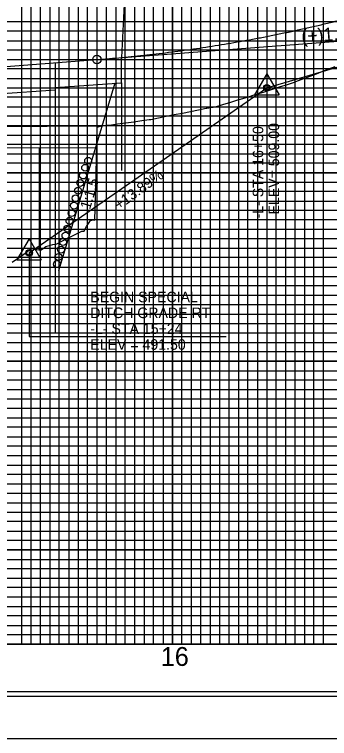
# Model space of a CAD drawing. Extents: x 573715 to 575626, y -55474 to -54374.
# Drawn here: x 574498.5 to 574665.5, y -55474.4 to -55090.5 of the extents above; entities that cross this region are included whole.
import ezdxf

# ---------------------------------------------------------------- set-up
doc = ezdxf.new("R2010")
doc.units = 0
for name, color, linetype in [('Default', 7, 'Continuous'), ('Exist Profile Cell', 7, 'Continuous'), ('Exist Vertical Profile Ground Line', 7, 'Continuous'), ('Exist Vertical Profile Horizontal Axis Label Major', 7, 'Continuous'), ('Prop Roadway Bridge', 7, 'Continuous'), ('Prop Vertical Profile Curve Label', 7, 'Continuous'), ('Prop Vertical Profile Ditch Grade Right', 7, 'Continuous'), ('Prop Vertical Profile Ditch Grade Right Label', 7, 'Continuous'), ('Prop Vertical Profile Grade', 7, 'Continuous'), ('Prop Vertical Profile Grade Label', 7, 'Continuous'), ('Prop VPI Label', 7, 'Continuous'), ('Sheet Cutting Line CELL', 7, 'Continuous'), ('Sheet DOT Grid CELL', 7, 'Continuous'), ('Sheet Layout Profile Border', 7, 'Continuous'), ('Sheet Plot Border Inside CELL', 7, 'Continuous'), ('Sheet Plot Border Outside CELL', 7, 'Continuous'), ('Sheet Profile CELL', 7, 'Continuous'), ('Sheet Profile Grid Major CELL', 7, 'Continuous'), ('Sheet Profile Grid Middle CELL', 7, 'Continuous'), ('Sheet Profile Grid Minor CELL', 7, 'Continuous')]:
    doc.layers.add(name, color=color, linetype=linetype)

msp = doc.modelspace()

# ---------------------------------------------------------------- linework, layer by layer
at = {"layer": 'Default'}
for p, q in [((574451.39, -55150.07), (574542.22, -55149.62)), ((574542.22, -55149.62), (574542.22, -55161.07)), ((574451.39, -55161.42), (574542.22, -55161.07)), ((574511.72, -55215.29), (574511.72, -55161.19))]:
    msp.add_line(p, q, dxfattribs=at)
at = {"layer": 'Exist Profile Cell'}
msp.add_line((573982.27, -55224.42), (575001.21, -55224.42), dxfattribs=at)
at = {"layer": 'Exist Vertical Profile Ground Line'}
msp.add_lwpolyline([(574497.4, -55221.8), (574501.76, -55218.83), (574503.47, -55217.66), (574506.04, -55215.68), (574507.55, -55214.53), (574509.69, -55214.98), (574510.33, -55215.08), (574512.36, -55215.4), (574513.67, -55214.64), (574514.62, -55213.84), (574515.08, -55213.45), (574518.91, -55212.56), (574520.92, -55212.09), (574523.2, -55210.94), (574527.49, -55208.8), (574531.78, -55206.66), (574534.29, -55205.41), (574535.47, -55205.43), (574536.07, -55204.23), (574536.71, -55202.96), (574538.79, -55199.75), (574540.36, -55199.33), (574541.14, -55199.65), (574541.75, -55174.95), (574542.35, -55150.23), (574544.65, -55149.63), (574547.64, -55149.29), (574548.94, -55149.12), (574553.23, -55148.54), (574557.52, -55147.95), (574561.81, -55147.37), (574566.1, -55146.79), (574569.92, -55146.27), (574570.39, -55146.19), (574570.87, -55146.12), (574574.89, -55145.31), (574578.96, -55144.49), (574583.25, -55143.63), (574587.54, -55142.77), (574591.83, -55141.91), (574596.12, -55141.05), (574600.05, -55140.26), (574600.41, -55140.2), (574604.87, -55139.51), (574606.92, -55138.93), (574608.99, -55138.28), (574613.28, -55136.93), (574616.99, -55135.76), (574617.57, -55135.6), (574622.07, -55134.32), (574626.15, -55133.03), (574630.44, -55131.67), (574634.73, -55130.31), (574639.02, -55128.94), (574643.3, -55127.57), (574646.95, -55126.4), (574647.68, -55126.11), (574651.97, -55124.45), (574655.22, -55123.19), (574658.56, -55121.9), (574661.89, -55120.61), (574665.23, -55119.33), (574668.57, -55118.05)], dxfattribs=at)
at = {"layer": 'Prop Roadway Bridge'}
for p, q in [((574555.29, -55126.77), (574555.29, -55113.31)), ((574520.29, -55129.22), (574520.29, -55116.08)), ((574520.29, -55129.22), (574555.29, -55126.77)), ((574551.76, -55127.02), (574521.93, -55226.45)), ((574555.29, -55126.77), (574555.29, -55173.26)), ((574450.29, -55135.37), (574520.29, -55130.47)), ((574520.29, -55259.24), (574520.29, -55129.22))]:
    msp.add_line(p, q, dxfattribs=at)
for centre in [(574537.6, -55168.09), (574535.99, -55171.81), (574534.87, -55175.9), (574533.38, -55179.86), (574532.27, -55183.95), (574530.91, -55187.92), (574530.04, -55191.88), (574528.8, -55195.85), (574527.69, -55199.93), (574526.57, -55204.02), (574524.22, -55211.21), (574525.58, -55207.74), (574523.23, -55215.18), (574521.12, -55222.86), (574521.87, -55219.14)]:
    msp.add_circle(centre, 1.83, dxfattribs=at)
at = {"layer": 'Prop Vertical Profile Curve Label'}
msp.add_circle((574542.27, -55114.41), 2.25, dxfattribs=at)
at = {"layer": 'Prop Vertical Profile Ditch Grade Right'}
msp.add_lwpolyline([(574506.27, -55216.92), (574632.27, -55129.42), (574782.27, -55085.27), (574907.27, -55010.97)], dxfattribs=at)
at = {"layer": 'Prop Vertical Profile Ditch Grade Right Label'}
for p, q in [((574632.27, -55121.94), (574625.82, -55133.14)), ((574632.27, -55121.94), (574638.77, -55133.14)), ((574632.27, -55129.42), (574632.27, -55200.04)), ((574632.27, -55129.42), (574632.27, -55200.04)), ((574625.82, -55133.14), (574638.77, -55133.14)), ((574506.27, -55209.44), (574499.82, -55220.64)), ((574506.27, -55209.44), (574512.77, -55220.64)), ((574506.27, -55216.92), (574506.27, -55261.31)), ((574499.82, -55220.64), (574512.77, -55220.64)), ((574506.27, -55261.31), (574610.74, -55261.31))]:
    msp.add_line(p, q, dxfattribs=at)
for centre, radius in [((574632.27, -55129.42), 1.75), ((574632.27, -55129.42), 1.2), ((574506.27, -55216.92), 1.75), ((574506.27, -55216.92), 1.2)]:
    msp.add_circle(centre, radius, dxfattribs=at)
at = {"layer": 'Prop Vertical Profile Grade'}
msp.add_line((574452.27, -55121.23), (574542.27, -55114.41), dxfattribs=at)
msp.add_spline([(574542.27, -55114.41), (574548.87, -55113.88), (574555.47, -55113.3), (574562.07, -55112.65), (574568.67, -55111.95), (574575.27, -55111.18), (574581.87, -55110.36), (574588.47, -55109.48), (574595.07, -55108.54), (574601.67, -55107.54), (574608.27, -55106.49), (574614.87, -55105.37), (574621.47, -55104.2), (574628.07, -55102.97), (574634.67, -55101.68), (574641.27, -55100.33), (574647.87, -55098.92), (574654.47, -55097.45), (574661.07, -55095.93), (574667.67, -55094.34), (574674.27, -55092.7), (574680.87, -55091), (574687.47, -55089.24), (574694.07, -55087.42), (574700.67, -55085.54), (574707.27, -55083.61), (574713.87, -55081.62), (574720.47, -55079.56), (574727.07, -55077.45), (574733.67, -55075.28), (574740.27, -55073.05), (574746.87, -55070.77), (574753.47, -55068.42), (574760.07, -55066.02), (574766.67, -55063.56), (574773.27, -55061.03), (574779.87, -55058.45), (574786.47, -55055.82), (574793.07, -55053.12), (574799.67, -55050.36), (574806.27, -55047.55), (574812.87, -55044.68), (574819.47, -55041.74), (574826.07, -55038.75), (574832.67, -55035.71), (574839.27, -55032.6), (574845.87, -55029.43), (574852.47, -55026.21), (574859.07, -55022.93), (574865.67, -55019.58), (574872.27, -55016.18)], degree=3, dxfattribs=at)
at = {"layer": 'Prop VPI Label'}
for p, q in [((574562.55, -54963.47), (574555.29, -55113.31)), ((574542.27, -55114.41), (574704.53, -55102.13))]:
    msp.add_line(p, q, dxfattribs=at)
at = {"layer": 'Sheet Cutting Line CELL'}
msp.add_line((573715.27, -55474.42), (575399.27, -55474.42), dxfattribs=at)
at = {"layer": 'Sheet DOT Grid CELL'}
for p, q in [((574532.27, -54399.42), (574532.27, -55424.42)), ((574582.27, -54399.42), (574582.27, -55424.42)), ((574632.27, -54399.42), (574632.27, -55424.42)), ((573882.27, -55124.42), (575382.27, -55124.42)), ((573882.27, -55174.42), (575382.27, -55174.42)), ((573882.27, -55224.42), (575382.27, -55224.42)), ((573882.27, -55274.42), (575382.27, -55274.42)), ((573882.27, -55324.42), (575382.27, -55324.42)), ((573882.27, -55374.42), (575382.27, -55374.42))]:
    msp.add_line(p, q, dxfattribs=at)
at = {"layer": 'Sheet Layout Profile Border'}
msp.add_lwpolyline([(573932.27, -54399.42), (573932.27, -55424.42), (575332.27, -55424.42), (575332.27, -54536.97), (575182.22, -54536.97), (575182.22, -54399.42)], close=True, dxfattribs=at)
at = {"layer": 'Sheet Plot Border Inside CELL'}
msp.add_lwpolyline([(575394.77, -54396.87), (573728.27, -54396.87), (573728.27, -55451.97), (575394.77, -55451.97)], close=True, dxfattribs=at)
msp.add_lwpolyline([(575394.77, -54396.87), (573728.27, -54396.87), (573728.27, -55451.97), (575394.77, -55451.97)], close=True, dxfattribs=at)
at = {"layer": 'Sheet Plot Border Outside CELL'}
msp.add_lwpolyline([(575399.27, -54374.42), (573715.27, -54374.42), (573715.27, -55474.42), (575399.27, -55474.42)], close=True, dxfattribs=at)
at = {"layer": 'Sheet Profile CELL'}
msp.add_line((575382.27, -55424.42), (573882.27, -55424.42), dxfattribs=at)
msp.add_lwpolyline([(575382.27, -54399.42), (573882.27, -54399.42), (573882.27, -55449.42), (575382.27, -55449.42)], close=True, dxfattribs=at)
at = {"layer": 'Sheet Profile Grid Major CELL'}
for points in [[(574532.27, -54399.42), (574532.27, -55424.42), (574582.27, -55424.42), (574582.27, -54399.42)], [(574632.27, -54399.42), (574632.27, -55424.42), (574682.27, -55424.42), (574682.27, -54399.42)], [(575382.27, -55174.42), (573882.27, -55174.42), (573882.27, -55124.42), (575382.27, -55124.42)], [(575382.27, -55274.42), (573882.27, -55274.42), (573882.27, -55224.42), (575382.27, -55224.42)], [(575382.27, -55374.42), (573882.27, -55374.42), (573882.27, -55324.42), (575382.27, -55324.42)]]:
    msp.add_lwpolyline(points, dxfattribs=at)
at = {"layer": 'Sheet Profile Grid Middle CELL'}
for points in [[(574507.27, -54399.42), (574507.27, -55424.42), (574557.27, -55424.42), (574557.27, -54399.42)], [(574607.27, -54399.42), (574607.27, -55424.42), (574657.27, -55424.42), (574657.27, -54399.42)], [(575382.27, -55099.42), (573882.27, -55099.42), (573882.27, -55149.42), (575382.27, -55149.42)], [(575382.27, -55199.42), (573882.27, -55199.42), (573882.27, -55249.42), (575382.27, -55249.42)], [(575382.27, -55299.42), (573882.27, -55299.42), (573882.27, -55349.42), (575382.27, -55349.42)], [(575382.27, -55399.42), (573882.27, -55399.42)]]:
    msp.add_lwpolyline(points, dxfattribs=at)
at = {"layer": 'Sheet Profile Grid Minor CELL'}
for points in [[(574502.27, -54399.42), (574502.27, -55424.42), (574512.27, -55424.42), (574512.27, -54399.42)], [(574517.27, -54399.42), (574517.27, -55424.42), (574522.27, -55424.42), (574522.27, -54399.42)], [(574527.27, -54399.42), (574527.27, -55424.42), (574537.27, -55424.42), (574537.27, -54399.42)], [(574542.27, -54399.42), (574542.27, -55424.42), (574547.27, -55424.42), (574547.27, -54399.42)], [(574552.27, -54399.42), (574552.27, -55424.42), (574562.27, -55424.42), (574562.27, -54399.42)], [(574567.27, -54399.42), (574567.27, -55424.42), (574572.27, -55424.42), (574572.27, -54399.42)], [(574577.27, -54399.42), (574577.27, -55424.42), (574587.27, -55424.42), (574587.27, -54399.42)], [(574592.27, -54399.42), (574592.27, -55424.42), (574597.27, -55424.42), (574597.27, -54399.42)], [(574602.27, -54399.42), (574602.27, -55424.42), (574612.27, -55424.42), (574612.27, -54399.42)], [(574617.27, -54399.42), (574617.27, -55424.42), (574622.27, -55424.42), (574622.27, -54399.42)], [(574627.27, -54399.42), (574627.27, -55424.42), (574637.27, -55424.42), (574637.27, -54399.42)], [(574642.27, -54399.42), (574642.27, -55424.42)], [(574652.27, -54400.02), (574652.27, -55424.42), (574662.27, -55424.42), (574662.27, -54399.42)], [(574642.27, -55424.42), (574647.27, -55424.42), (574647.27, -54400.02)], [(575332.27, -55094.42), (573932.27, -55094.42), (573932.27, -55104.42), (575332.27, -55104.42)], [(575332.27, -55109.42), (573932.27, -55109.42), (573932.27, -55114.42), (575332.27, -55114.42)], [(575332.27, -55119.42), (573932.27, -55119.42), (573932.27, -55129.42), (575332.27, -55129.42)], [(575332.27, -55134.42), (573932.27, -55134.42), (573932.27, -55139.42), (575332.27, -55139.42)], [(575332.27, -55144.42), (573932.27, -55144.42), (573932.27, -55154.42), (575332.27, -55154.42)], [(575332.27, -55159.42), (573932.27, -55159.42), (573932.27, -55164.42), (575332.27, -55164.42)], [(575332.27, -55169.42), (573932.27, -55169.42), (573932.27, -55179.42), (575332.27, -55179.42)], [(575332.27, -55184.42), (573932.27, -55184.42), (573932.27, -55189.42), (575332.27, -55189.42)], [(575332.27, -55194.42), (573932.27, -55194.42), (573932.27, -55204.42), (575332.27, -55204.42)], [(575332.27, -55209.42), (573932.27, -55209.42), (573932.27, -55214.42), (575332.27, -55214.42)], [(575332.27, -55219.42), (573932.27, -55219.42)], [(573932.27, -55229.42), (575332.27, -55229.42)], [(575332.27, -55234.42), (573932.27, -55234.42), (573932.27, -55239.42), (575332.27, -55239.42)], [(575332.27, -55244.42), (573932.27, -55244.42)], [(573932.27, -55254.42), (575332.27, -55254.42)], [(575332.27, -55259.42), (573932.27, -55259.42), (573932.27, -55264.42), (575332.27, -55264.42)], [(575332.27, -55269.42), (573932.27, -55269.42), (573932.27, -55279.42), (575332.27, -55279.42)], [(575332.27, -55284.42), (573932.27, -55284.42), (573932.27, -55289.42), (575332.27, -55289.42)], [(575332.27, -55294.42), (573932.27, -55294.42), (573932.27, -55304.42), (575332.27, -55304.42)], [(575332.27, -55309.42), (573932.27, -55309.42), (573932.27, -55314.42), (575332.27, -55314.42)], [(575332.27, -55319.42), (573932.27, -55319.42), (573932.27, -55329.42), (575332.27, -55329.42)], [(575332.27, -55334.42), (573932.27, -55334.42), (573932.27, -55339.42), (575332.27, -55339.42)], [(575332.27, -55344.42), (573932.27, -55344.42), (573932.27, -55354.42), (575332.27, -55354.42)], [(575332.27, -55359.42), (573932.27, -55359.42), (573932.27, -55364.42), (575332.27, -55364.42)], [(575332.27, -55369.42), (573932.27, -55369.42), (573932.27, -55379.42), (575332.27, -55379.42)], [(575332.27, -55384.42), (573932.27, -55384.42), (573932.27, -55389.42), (575332.27, -55389.42)], [(575332.27, -55394.42), (573932.27, -55394.42), (573932.27, -55404.42), (575332.27, -55404.42)], [(575332.27, -55409.42), (573932.27, -55409.42), (573932.27, -55414.42), (575332.27, -55414.42)], [(575332.27, -55419.42), (573932.27, -55419.42)]]:
    msp.add_lwpolyline(points, dxfattribs=at)

# ---------------------------------------------------------------- texts
at = {"layer": 'Exist Vertical Profile Horizontal Axis Label Major'}
msp.add_text('16', height=10, dxfattribs=at).set_placement((574576.06, -55435.92))
at = {"layer": 'Prop Roadway Bridge'}
msp.add_text('1:1.5', height=5.6, rotation=73.3008, dxfattribs=at).set_placement((574538.55, -55194.19))
at = {"layer": 'Prop Vertical Profile Ditch Grade Right'}
msp.add_text('+13.89%', height=5.6, rotation=35.8927, dxfattribs=at).set_placement((574553.92, -55194.32))
at = {"layer": 'Prop Vertical Profile Ditch Grade Right Label'}
for s, p in [('-L- STA 16+50', (574630.4, -55198.65)), (' ELEV= 509.00', (574638.8, -55198.65))]:
    msp.add_text(s, height=5.6, rotation=90, dxfattribs=at).set_placement(p)
for s, p in [('BEGIN SPECIAL', (574538.71, -55243.1)), ('DITCH GRADE RT', (574538.71, -55251.5)), ('-L- STA 15+24', (574538.71, -55259.9)), ('ELEV = 491.50', (574538.71, -55268.3))]:
    msp.add_text(s, height=5.6, dxfattribs=at).set_placement(p)
at = {"layer": 'Prop Vertical Profile Grade Label'}
msp.add_text('(+)1.5143%', height=7, rotation=4.3298, dxfattribs=at).set_placement((574650.88, -55105.62))

doc.saveas('drawing.dxf')
